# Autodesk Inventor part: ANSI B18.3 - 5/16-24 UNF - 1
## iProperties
Created: 2005-03
Part Number: ANSI B18.3 - 5/16-24 UNF - 1
Material: Steel, Mild
Description: Hexagon Socket Head Cap Screw
Vendor: Autodesk Inc.
Document SubType Name: Modeling
Standard: ANSI B18.3
Designer: Admin
Standards Organization: ANSI
Language: en-US
Size Designation: 5/16-24 UNF - 1
Categories: <MemberInstance Version="R10.0.0"><Categories><Category DisplayName="Fasteners" InternalName="e4da775c-781d-43d5-af7c-5136215cf5a6" Mnemonic="FSTN"><Category Di
Density: 1 g/cm^3
Author: Admin
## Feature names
1. Body [Revolution]
2. Slot [Extrusion]
3. Fillet1
4. Chamfer1
